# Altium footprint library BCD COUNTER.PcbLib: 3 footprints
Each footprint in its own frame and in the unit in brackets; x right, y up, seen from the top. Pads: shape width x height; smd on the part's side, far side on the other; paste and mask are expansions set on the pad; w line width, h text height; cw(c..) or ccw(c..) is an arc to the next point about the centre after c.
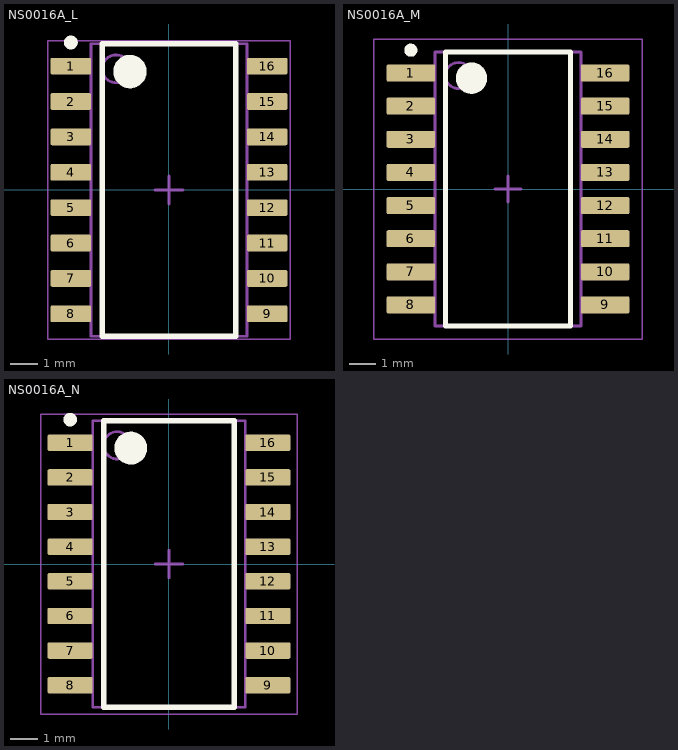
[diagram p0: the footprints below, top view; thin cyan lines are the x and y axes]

## NS0016A_L [mm] "SOIC,16-Leads,Body 10.5x5.6mm,Pitch 1.27mm,IPC High Density"
height 2
pads (16):
  rrect17% 1.45x0.6 smd: 1(-3.525,4.445) 2(-3.525,3.175) 3(-3.525,1.905) 4(-3.525,0.635) 5(-3.525,-0.635) 6(-3.525,-1.905) 7(-3.525,-3.175) 8(-3.525,-4.445) 9(3.525,-4.445) 10(3.525,-3.175) 11(3.525,-1.905) 12(3.525,-0.635) 13(3.525,0.635) 14(3.525,1.905) 15(3.525,3.175) 16(3.525,4.445)
Top Overlay:
  circle w0.6: c-1.4,4.25 r0.3
  circle w0.25: c-3.525,5.295 r0.125
  lines w0.2: -2.4,-5.25 2.4,-5.25 2.4,5.25 -2.4,5.25 -2.4,-5.25
Mechanical 1:
  text ".Designator" at -1.524,-0.508 h1.02
Mechanical 13:
  circle w0.1: c-1.9,4.35 r0.5
  lines w0.1: -2.8,-5.25 2.8,-5.25 2.8,5.25 -2.8,5.25 -2.8,-5.25
Mechanical 15:
  lines w0.05: -4.35,-5.35 4.35,-5.35 4.35,5.35 -4.35,5.35 -4.35,-5.35
  lines w0.1: -0.5,0 0.5,0 ; 0,-0.5 0,0.5
3D body: height 2, standoff 0.05, extent -2.8,-5.25 2.8,5.25

## NS0016A_M [mm] "SOIC,16-Leads,Body 10.5x5.6mm,Pitch 1.27mm,IPC Low Density"
height 2
pads (16):
  rrect15% 1.85x0.65 smd: 1(-3.725,4.445) 2(-3.725,3.175) 3(-3.725,1.905) 4(-3.725,0.635) 5(-3.725,-0.635) 6(-3.725,-1.905) 7(-3.725,-3.175) 8(-3.725,-4.445) 9(3.725,-4.445) 10(3.725,-3.175) 11(3.725,-1.905) 12(3.725,-0.635) 13(3.725,0.635) 14(3.725,1.905) 15(3.725,3.175) 16(3.725,4.445)
Top Overlay:
  circle w0.6: c-1.4,4.25 r0.3
  circle w0.25: c-3.725,5.32 r0.125
  lines w0.2: -2.4,-5.25 2.4,-5.25 2.4,5.25 -2.4,5.25 -2.4,-5.25
Mechanical 1:
  text ".Designator" at -1.524,-0.508 h1.02
Mechanical 13:
  circle w0.1: c-1.9,4.35 r0.5
  lines w0.1: -2.8,-5.25 2.8,-5.25 2.8,5.25 -2.8,5.25 -2.8,-5.25
Mechanical 15:
  lines w0.05: -5.15,-5.75 5.15,-5.75 5.15,5.75 -5.15,5.75 -5.15,-5.75
  lines w0.1: -0.5,0 0.5,0 ; 0,-0.5 0,0.5
3D body: height 2, standoff 0.05, extent -2.8,-5.25 2.8,5.25

## NS0016A_N [mm] "SOIC,16-Leads,Body 10.5x5.6mm,Pitch 1.27mm,IPC Medium Density"
height 2
pads (16):
  rrect17% 1.65x0.6 smd: 1(-3.625,4.445) 2(-3.625,3.175) 3(-3.625,1.905) 4(-3.625,0.635) 5(-3.625,-0.635) 6(-3.625,-1.905) 7(-3.625,-3.175) 8(-3.625,-4.445) 9(3.625,-4.445) 10(3.625,-3.175) 11(3.625,-1.905) 12(3.625,-0.635) 13(3.625,0.635) 14(3.625,1.905) 15(3.625,3.175) 16(3.625,4.445)
Top Overlay:
  circle w0.6: c-1.4,4.25 r0.3
  circle w0.25: c-3.625,5.295 r0.125
  lines w0.2: -2.4,-5.25 2.4,-5.25 2.4,5.25 -2.4,5.25 -2.4,-5.25
Mechanical 1:
  text ".Designator" at -1.524,-0.508 h1.02
Mechanical 13:
  circle w0.1: c-1.9,4.35 r0.5
  lines w0.1: -2.8,-5.25 2.8,-5.25 2.8,5.25 -2.8,5.25 -2.8,-5.25
Mechanical 15:
  lines w0.05: -4.7,-5.5 4.7,-5.5 4.7,5.5 -4.7,5.5 -4.7,-5.5
  lines w0.1: -0.5,0 0.5,0 ; 0,-0.5 0,0.5
3D body: height 2, standoff 0.05, extent -2.8,-5.25 2.8,5.25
